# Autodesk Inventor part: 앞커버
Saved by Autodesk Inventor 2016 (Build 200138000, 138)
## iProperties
Created: 2024-08
Part Number: 앞커버
Material: 일반
Document SubType Name: Modeling
Designer: pc-2
Density: 1 g/cm^3
Appearance: 기본값
Author: jhkim
Sending System: Autodesk Inventor 2025
Preprocessor: ST-DEVELOPER v20
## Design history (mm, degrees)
node "앞커버1"
node "솔리드2"
node "솔리드1"
